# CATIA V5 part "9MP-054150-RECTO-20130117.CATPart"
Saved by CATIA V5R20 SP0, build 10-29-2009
Part number: 9MP-054150-RECTO-20130117
Revision: ANY
Definition: UNKNOWN
Nomenclature: 9MP-054150-RECTO-20130117
Source: Unknown
Bounding box of the stored display mesh (mm): x 1030.842 to 1180.842, y 1497.779 to 1501.779, z 0 to 5
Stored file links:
  C:\Users\Utente\Desktop\IO LAVORO\3D X SITO CF\CUMSA\3D files PF\PF 054150\9MP-054150-RECTO-20130117.CATPart
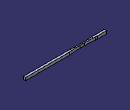
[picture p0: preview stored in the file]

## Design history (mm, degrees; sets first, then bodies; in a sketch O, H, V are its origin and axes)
Body1 "Cortar-Extruir1" (main body)
  Solid1: solid without history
